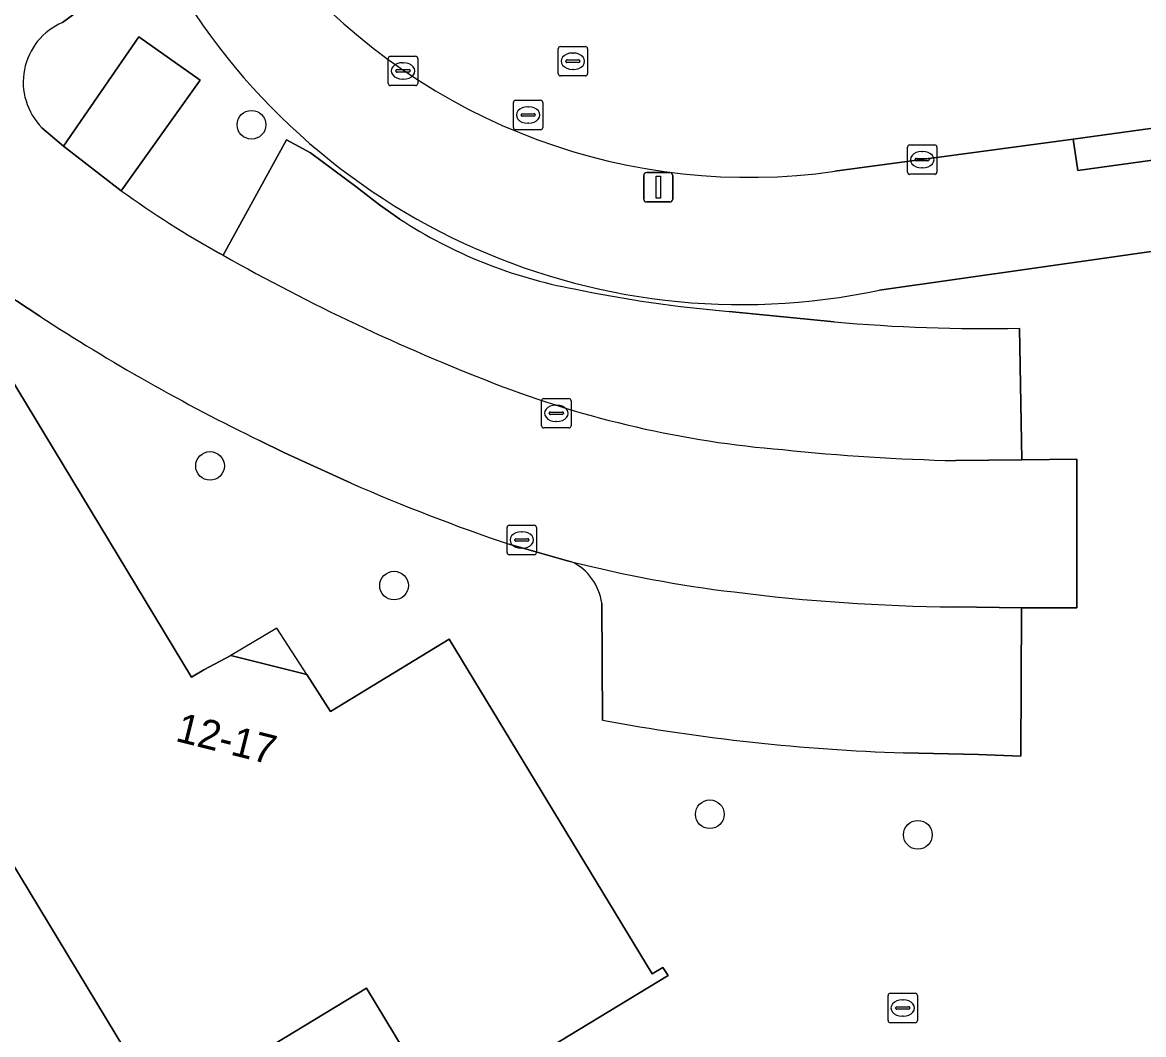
# Model space of a CAD drawing. Extents: x 158455 to 159797, y 387218 to 388672.
# Drawn here: x 158871.25 to 158909.44, y 387418.37 to 387452.85 of the extents above; entities that cross this region are included whole.
import ezdxf

# ---------------------------------------------------------------- set-up
doc = ezdxf.new("R2010")
doc.units = 0
for name, color, linetype in [('IMGEO_Boom', 7, 'Continuous'), ('IMGEO_Erf', 7, 'Continuous'), ('IMGEO_Groenvoorziening', 7, 'Continuous'), ('IMGEO_Kolk', 7, 'Continuous'), ('IMGEO_Lichtmast', 7, 'Continuous'), ('IMGEO_Pand', 7, 'Continuous'), ('IMGEO_Pand_nummerreeks', 7, 'Continuous'), ('IMGEO_Pand_overbouw', 7, 'Continuous'), ('IMGEO_Parkeervlak_open', 7, 'Continuous'), ('IMGEO_Rijbaan_lokaal_gesloten', 7, 'Continuous'), ('IMGEO_Rijbaan_lokaal_open', 7, 'Continuous'), ('IMGEO_Rioolput', 7, 'Continuous'), ('IMGEO_Voetpad_open', 7, 'Continuous')]:
    doc.layers.add(name, color=color, linetype=linetype)

msp = doc.modelspace()

# ---------------------------------------------------------------- linework, layer by layer
at = {"layer": 'IMGEO_Boom'}
for centre in [(158879.053, 387449.361), (158877.643, 387437.739), (158883.91, 387433.662), (158894.666, 387425.871), (158901.753, 387425.172)]:
    msp.add_circle(centre, 0.489, dxfattribs=at)
at = {"layer": 'IMGEO_Erf'}
for points in [[(159004.113, 387458.902), (158999.01, 387458.217), (158989.379, 387456.925), (158973.012, 387454.73), (158964.768, 387453.624), (158962.694, 387453.346), (158918.158, 387447.372), (158913.387, 387446.696), (158913.533, 387445.59), (158900.447, 387443.729)], [(158875.925, 387455.143), (158875.861, 387455.245), (158872.617, 387452.848)], [(158871.917, 387449.258), (158872.651, 387448.631), (158875.213, 387452.359), (158877.303, 387450.882), (158874.613, 387447.115)], [(158877.975, 387444.977), (158878.087, 387444.914), (158880.247, 387448.844), (158881.066, 387448.407), (158882.606, 387447.258), (158883.419, 387446.633), (158884.105, 387446.148)], [(158871.848, 387442.837), (158871.448, 387443.1), (158871.049, 387443.366)], [(158895.32, 387443.002), (158898.898, 387442.649)], [(158905.213, 387442.429), (158905.298, 387437.945), (158907.163, 387437.965), (158907.173, 387432.899), (158905.283, 387432.906), (158905.262, 387427.848), (158903.819, 387427.906), (158901.265, 387427.965)], [(158870.128, 387441.906), (158877.011, 387430.547), (158877.433, 387430.797), (158878.349, 387431.277), (158880.936, 387430.633), (158881.749, 387429.377), (158885.792, 387431.831), (158892.702, 387420.438), (158893.07, 387420.653), (158893.246, 387420.373), (158885.536, 387415.704)], [(158882.452, 387437.149), (158880.157, 387438.198), (158879.331, 387438.601)], [(158889.956, 387434.475), (158889.769, 387434.522), (158887.835, 387435.068)], [(158891.013, 387429.079), (158890.986, 387433.06)]]:
    msp.add_lwpolyline(points, dxfattribs=at)
for centre, radius, start, end in [((158895.756, 387465.7), 22.466, 208.0279, 282.052), ((158873.495, 387450.814), 2.216, 113.3331, 224.6), ((158895.375, 387476.052), 35.615, 234.3399, 240.753), ((158893.085, 387459.953), 16.469, 236.9555, 259.3652), ((158899.016, 387487.043), 44.195, 258.2902, 265.2033), ((158909.388, 387500.426), 68.744, 236.9008, 244.07226), ((158904.027, 387499.132), 56.715, 264.8113, 271.1982), ((158909.446, 387498.973), 67.46, 246.41253, 251.31572), ((158889.163, 387432.815), 1.839, 7.6405, 64.4623), ((158903.488, 387496.149), 68.221, 259.46387, 268.13308)]:
    msp.add_arc(centre, radius, start, end, dxfattribs=at)
at = {"layer": 'IMGEO_Groenvoorziening'}
msp.add_lwpolyline([(158878.756, 387417.394), (158881.325, 387413.154), (158885.536, 387415.704), (158882.967, 387419.945)], close=True, dxfattribs=at)
at = {"layer": 'IMGEO_Kolk'}
for p, q in [((158883.715, 387450.77), (158883.715, 387451.622)), ((158883.79, 387451.696), (158884.642, 387451.696)), ((158884.716, 387451.622), (158884.716, 387450.77)), ((158884.017, 387451.239), (158884.415, 387451.239)), ((158884.203, 387451.476), (158884.228, 387451.476)), ((158883.974, 387451.19), (158883.974, 387451.202)), ((158884.412, 387451.153), (158884.014, 387451.153)), ((158884.226, 387450.916), (158884.201, 387450.916)), ((158884.458, 387451.202), (158884.458, 387451.19)), ((158884.642, 387450.696), (158883.79, 387450.696)), ((158901.401, 387447.747), (158901.401, 387448.599)), ((158901.476, 387448.673), (158902.328, 387448.673)), ((158902.402, 387448.599), (158902.402, 387447.747)), ((158901.66, 387448.167), (158901.66, 387448.179)), ((158901.703, 387448.216), (158902.101, 387448.216)), ((158901.889, 387448.453), (158901.914, 387448.453)), ((158902.144, 387448.179), (158902.144, 387448.167)), ((158902.098, 387448.13), (158901.7, 387448.13)), ((158901.912, 387447.893), (158901.887, 387447.893)), ((158902.328, 387447.673), (158901.476, 387447.673)), ((158888.938, 387439.106), (158888.938, 387439.958)), ((158889.013, 387440.032), (158889.865, 387440.032)), ((158889.426, 387439.812), (158889.451, 387439.812)), ((158889.939, 387439.958), (158889.939, 387439.106)), ((158889.197, 387439.526), (158889.197, 387439.538)), ((158889.635, 387439.489), (158889.237, 387439.489)), ((158889.24, 387439.575), (158889.638, 387439.575)), ((158889.681, 387439.538), (158889.681, 387439.526)), ((158889.865, 387439.032), (158889.013, 387439.032)), ((158889.449, 387439.252), (158889.424, 387439.252)), ((158887.76, 387434.789), (158887.76, 387435.641)), ((158887.835, 387435.715), (158888.687, 387435.715)), ((158888.761, 387435.641), (158888.761, 387434.789)), ((158888.019, 387435.209), (158888.019, 387435.221)), ((158888.062, 387435.258), (158888.46, 387435.258)), ((158888.248, 387435.495), (158888.273, 387435.495)), ((158888.503, 387435.221), (158888.503, 387435.209)), ((158888.457, 387435.172), (158888.059, 387435.172)), ((158888.271, 387434.935), (158888.246, 387434.935)), ((158888.687, 387434.715), (158887.835, 387434.715)), ((158900.737, 387418.845), (158900.737, 387419.697)), ((158900.812, 387419.771), (158901.664, 387419.771)), ((158901.225, 387419.551), (158901.25, 387419.551)), ((158901.738, 387419.697), (158901.738, 387418.845)), ((158900.996, 387419.265), (158900.996, 387419.277)), ((158901.434, 387419.228), (158901.036, 387419.228)), ((158901.039, 387419.314), (158901.437, 387419.314)), ((158901.48, 387419.277), (158901.48, 387419.265)), ((158901.664, 387418.771), (158900.812, 387418.771)), ((158901.248, 387418.991), (158901.223, 387418.991))]:
    msp.add_line(p, q, dxfattribs=at)
for points in [[(158883.715, 387450.77), (158883.715, 387451.622)], [(158883.79, 387451.696), (158884.642, 387451.696)], [(158884.716, 387451.622), (158884.716, 387450.77)], [(158884.642, 387450.696), (158883.79, 387450.696)], [(158901.401, 387447.747), (158901.401, 387448.599)], [(158901.476, 387448.673), (158902.328, 387448.673)], [(158902.402, 387448.599), (158902.402, 387447.747)], [(158902.328, 387447.673), (158901.476, 387447.673)], [(158888.938, 387439.106), (158888.938, 387439.958)], [(158889.013, 387440.032), (158889.865, 387440.032)], [(158889.939, 387439.958), (158889.939, 387439.106)], [(158889.865, 387439.032), (158889.013, 387439.032)], [(158887.76, 387434.789), (158887.76, 387435.641)], [(158887.835, 387435.715), (158888.687, 387435.715)], [(158888.761, 387435.641), (158888.761, 387434.789)], [(158888.687, 387434.715), (158887.835, 387434.715)], [(158900.737, 387418.845), (158900.737, 387419.697)], [(158900.812, 387419.771), (158901.664, 387419.771)], [(158901.738, 387419.697), (158901.738, 387418.845)], [(158901.664, 387418.771), (158900.812, 387418.771)]]:
    msp.add_lwpolyline(points, dxfattribs=at)
for centre, radius, start, end in [((158883.792, 387451.62), 0.0765, 91.552, 178.448), ((158883.792, 387451.62), 0.0765, 91.552, 178.448), ((158884.64, 387451.62), 0.0765, 1.552, 88.448), ((158884.64, 387451.62), 0.0765, 1.552, 88.448), ((158884.014, 387451.199), 0.0403, 85.8775, 175.7526), ((158884.419, 387451.201), 0.0386, 1.7309, 96.639), ((158884.011, 387451.189), 0.0366, 178.938, 274.7102), ((158884.415, 387451.196), 0.043, 264.8664, 352.4533), ((158883.792, 387450.772), 0.0765, 181.552, 268.448), ((158883.792, 387450.772), 0.0765, 181.552, 268.448), ((158884.64, 387450.772), 0.0765, 271.552, 358.448), ((158884.64, 387450.772), 0.0765, 271.552, 358.448), ((158901.478, 387448.597), 0.0765, 91.552, 178.448), ((158901.478, 387448.597), 0.0765, 91.552, 178.448), ((158902.326, 387448.597), 0.0765, 1.552, 88.448), ((158902.326, 387448.597), 0.0765, 1.552, 88.448), ((158901.7, 387448.176), 0.0403, 85.8775, 175.7526), ((158902.105, 387448.178), 0.0386, 1.7309, 96.639), ((158901.697, 387448.166), 0.0366, 178.938, 274.7102), ((158902.101, 387448.173), 0.043, 264.8664, 352.4533), ((158901.478, 387447.749), 0.0765, 181.552, 268.448), ((158901.478, 387447.749), 0.0765, 181.552, 268.448), ((158902.326, 387447.749), 0.0765, 271.552, 358.448), ((158902.326, 387447.749), 0.0765, 271.552, 358.448), ((158889.015, 387439.956), 0.0765, 91.552, 178.448), ((158889.015, 387439.956), 0.0765, 91.552, 178.448), ((158889.863, 387439.956), 0.0765, 1.552, 88.448), ((158889.863, 387439.956), 0.0765, 1.552, 88.448), ((158889.237, 387439.535), 0.0403, 85.8775, 175.7526), ((158889.234, 387439.525), 0.0366, 178.938, 274.7102), ((158889.638, 387439.532), 0.043, 264.8664, 352.4533), ((158889.642, 387439.537), 0.0386, 1.7309, 96.639), ((158889.015, 387439.108), 0.0765, 181.552, 268.448), ((158889.015, 387439.108), 0.0765, 181.552, 268.448), ((158889.863, 387439.108), 0.0765, 271.552, 358.448), ((158889.863, 387439.108), 0.0765, 271.552, 358.448), ((158887.837, 387435.639), 0.0765, 91.552, 178.448), ((158887.837, 387435.639), 0.0765, 91.552, 178.448), ((158888.685, 387435.639), 0.0765, 1.552, 88.448), ((158888.685, 387435.639), 0.0765, 1.552, 88.448), ((158888.059, 387435.218), 0.0403, 85.8775, 175.7526), ((158888.056, 387435.208), 0.0366, 178.938, 274.7102), ((158888.46, 387435.215), 0.043, 264.8664, 352.4533), ((158888.464, 387435.22), 0.0386, 1.7309, 96.639), ((158887.837, 387434.791), 0.0765, 181.552, 268.448), ((158887.837, 387434.791), 0.0765, 181.552, 268.448), ((158888.685, 387434.791), 0.0765, 271.552, 358.448), ((158888.685, 387434.791), 0.0765, 271.552, 358.448), ((158900.814, 387419.695), 0.0765, 91.552, 178.448), ((158900.814, 387419.695), 0.0765, 91.552, 178.448), ((158901.662, 387419.695), 0.0765, 1.552, 88.448), ((158901.662, 387419.695), 0.0765, 1.552, 88.448), ((158901.036, 387419.274), 0.0403, 85.8775, 175.7526), ((158901.033, 387419.264), 0.0366, 178.938, 274.7102), ((158901.437, 387419.271), 0.043, 264.8664, 352.4533), ((158901.441, 387419.276), 0.0386, 1.7309, 96.639), ((158900.814, 387418.847), 0.0765, 181.552, 268.448), ((158900.814, 387418.847), 0.0765, 181.552, 268.448), ((158901.662, 387418.847), 0.0765, 271.552, 358.448), ((158901.662, 387418.847), 0.0765, 271.552, 358.448)]:
    msp.add_arc(centre, radius, start, end, dxfattribs=at)
for centre, major_axis, ratio, start_param, end_param in [((158884.202, 387451.196), (-0.387, 0.002), 0.722429, 4.712389, 7.853982), ((158884.227, 387451.196), (-0.39, 0.002), 0.717154, 1.570796, 4.712389), ((158901.888, 387448.173), (-0.387, 0.002), 0.722429, 4.712389, 7.853982), ((158901.913, 387448.173), (-0.39, 0.002), 0.717154, 1.570796, 4.712389), ((158889.425, 387439.532), (-0.387, 0.002), 0.722429, 4.712389, 7.853982), ((158889.45, 387439.532), (-0.39, 0.002), 0.717154, 1.570796, 4.712389), ((158888.247, 387435.215), (-0.387, 0.002), 0.722429, 4.712389, 7.853982), ((158888.272, 387435.215), (-0.39, 0.002), 0.717154, 1.570796, 4.712389), ((158901.224, 387419.271), (-0.387, 0.002), 0.722429, 4.712389, 7.853982), ((158901.249, 387419.271), (-0.39, 0.002), 0.717154, 1.570796, 4.712389)]:
    msp.add_ellipse(centre, major_axis=major_axis, ratio=ratio, start_param=start_param, end_param=end_param, dxfattribs=at)
at = {"layer": 'IMGEO_Lichtmast'}
for p, q in [((158892.416, 387446.832), (158892.416, 387447.632)), ((158892.416, 387447.632), (158892.416, 387446.832)), ((158892.516, 387447.732), (158893.306, 387447.732)), ((158893.306, 387447.732), (158892.516, 387447.732)), ((158893.406, 387447.632), (158893.406, 387446.832)), ((158893.406, 387446.832), (158893.406, 387447.632)), ((158893.306, 387446.732), (158892.516, 387446.732)), ((158892.516, 387446.732), (158893.306, 387446.732))]:
    msp.add_line(p, q, dxfattribs=at)
msp.add_lwpolyline([(158892.836, 387447.607), (158892.986, 387447.607), (158892.986, 387446.857), (158892.836, 387446.857), (158892.836, 387447.607)], dxfattribs=at)
for centre, start, end in [((158892.516, 387447.632), 90, 180), ((158892.516, 387447.632), 90, 180), ((158893.306, 387447.632), 0, 90), ((158893.306, 387447.632), 360, 90), ((158892.516, 387446.832), 180, 270), ((158892.516, 387446.832), 180, 270), ((158893.306, 387446.832), 270, 0), ((158893.306, 387446.832), 270, 0)]:
    msp.add_arc(centre, 0.1, start, end, dxfattribs=at)
at = {"layer": 'IMGEO_Pand'}
for points in [[(158876.19, 387415.839), (158878.756, 387417.394), (158882.967, 387419.945), (158885.536, 387415.704), (158893.246, 387420.373), (158893.07, 387420.653), (158892.702, 387420.438), (158885.792, 387431.831), (158881.749, 387429.377), (158880.936, 387430.633), (158878.349, 387431.277), (158877.433, 387430.797), (158877.011, 387430.547), (158870.128, 387441.906), (158863.221, 387437.75), (158862.731, 387437.455), (158865.617, 387432.671), (158867.166, 387430.102), (158867.288, 387430.172), (158876.018, 387415.735)], [(158876.19, 387415.839), (158876.018, 387415.735), (158867.288, 387430.172), (158867.166, 387430.102), (158862.332, 387427.187), (158861.702, 387428.232), (158861.172, 387427.912), (158860.62, 387428.828), (158861.15, 387429.148), (158860.783, 387429.756), (158858.526, 387433.498), (158851.265, 387429.143), (158855.262, 387422.534), (158856.931, 387423.54), (158869.412, 387402.893), (158880.123, 387409.348), (158879.537, 387410.315)]]:
    msp.add_lwpolyline(points, close=True, dxfattribs=at)
at = {"layer": 'IMGEO_Pand_overbouw'}
msp.add_lwpolyline([(158879.918, 387432.206), (158878.349, 387431.277), (158880.936, 387430.633)], close=True, dxfattribs=at)
at = {"layer": 'IMGEO_Parkeervlak_open'}
msp.add_lwpolyline([(158877.303, 387450.882), (158875.213, 387452.359), (158872.651, 387448.631), (158874.613, 387447.115)], close=True, dxfattribs=at)
for points in [[(158884.105, 387446.148), (158883.419, 387446.633), (158882.606, 387447.258), (158881.066, 387448.407), (158880.247, 387448.844), (158878.087, 387444.914)], [(158898.898, 387442.649), (158895.32, 387443.002)], [(158903.048, 387437.92), (158905.298, 387437.945), (158905.213, 387442.429)], [(158890.986, 387433.06), (158891.013, 387429.079)], [(158901.265, 387427.965), (158903.819, 387427.906), (158905.262, 387427.848), (158905.283, 387432.906), (158902.988, 387432.936)]]:
    msp.add_lwpolyline(points, dxfattribs=at)
for centre, radius, start, end in [((158893.085, 387459.953), 16.469, 236.9555, 259.3652), ((158912.992, 387506.857), 71.101, 240.59836, 248.83577), ((158899.016, 387487.043), 44.195, 258.2902, 265.2033), ((158904.027, 387499.132), 56.715, 264.8113, 271.1982), ((158899.982, 387473.124), 34.946, 248.7602, 265.3553), ((158904.496, 387507.598), 69.693, 263.95092, 268.80929), ((158900.785, 387477.245), 44.12, 255.7914, 263.1093), ((158889.163, 387432.815), 1.839, 7.6405, 64.4623), ((158903.686, 387498.789), 65.857, 262.85301, 269.39304), ((158903.488, 387496.149), 68.221, 259.46387, 268.13308)]:
    msp.add_arc(centre, radius, start, end, dxfattribs=at)
at = {"layer": 'IMGEO_Rijbaan_lokaal_gesloten'}
msp.add_lwpolyline([(158898.93, 387447.778), (158907.04, 387448.873), (158912.798, 387449.665), (158912.567, 387451.122), (158994.092, 387462.187)], dxfattribs=at)
msp.add_arc((158895.992, 387468.359), 20.79, 221.2558, 278.1232, dxfattribs=at)
at = {"layer": 'IMGEO_Rijbaan_lokaal_open'}
for points in [[(158872.617, 387452.848), (158875.861, 387455.245), (158872.628, 387460.413), (158853.054, 387445.81), (158834.448, 387431.91), (158827.832, 387426.967), (158817.674, 387419.378)], [(158874.613, 387447.115), (158872.651, 387448.631), (158871.917, 387449.258)], [(158841.258, 387429.496), (158843.407, 387431.102), (158865.405, 387447.54), (158865.534, 387447.366), (158868.364, 387443.543), (158869.559, 387444.453), (158871.049, 387443.366), (158871.448, 387443.1), (158871.848, 387442.837)], [(158878.087, 387444.914), (158877.975, 387444.977)], [(158879.331, 387438.601), (158880.157, 387438.198), (158882.452, 387437.149)], [(158902.988, 387432.936), (158905.283, 387432.906), (158907.173, 387432.899), (158907.163, 387437.965), (158905.298, 387437.945), (158903.048, 387437.92)], [(158887.835, 387435.068), (158889.769, 387434.522), (158889.956, 387434.475)]]:
    msp.add_lwpolyline(points, dxfattribs=at)
for centre, radius, start, end in [((158873.495, 387450.814), 2.216, 113.3331, 224.6), ((158895.375, 387476.052), 35.615, 234.3399, 240.753), ((158912.992, 387506.857), 71.101, 240.59836, 248.83577), ((158909.388, 387500.426), 68.744, 236.9008, 244.07226), ((158899.982, 387473.124), 34.946, 248.7602, 265.3553), ((158904.496, 387507.598), 69.693, 263.95092, 268.80929), ((158909.446, 387498.973), 67.46, 246.41253, 251.31572), ((158900.785, 387477.245), 44.12, 255.7914, 263.1093), ((158903.686, 387498.789), 65.857, 262.85301, 269.39304)]:
    msp.add_arc(centre, radius, start, end, dxfattribs=at)
at = {"layer": 'IMGEO_Rioolput'}
for p, q in [((158889.575, 387452.026), (158890.427, 387452.026)), ((158889.5, 387451.1), (158889.5, 387451.952)), ((158889.988, 387451.806), (158890.013, 387451.806)), ((158890.501, 387451.952), (158890.501, 387451.1)), ((158889.759, 387451.52), (158889.759, 387451.532)), ((158890.197, 387451.483), (158889.799, 387451.483)), ((158889.802, 387451.569), (158890.2, 387451.569)), ((158890.011, 387451.246), (158889.986, 387451.246)), ((158890.243, 387451.532), (158890.243, 387451.52)), ((158890.427, 387451.026), (158889.575, 387451.026)), ((158887.976, 387449.268), (158887.976, 387450.12)), ((158888.051, 387450.194), (158888.903, 387450.194)), ((158888.977, 387450.12), (158888.977, 387449.268)), ((158888.278, 387449.737), (158888.676, 387449.737)), ((158888.464, 387449.974), (158888.489, 387449.974)), ((158888.235, 387449.688), (158888.235, 387449.7)), ((158888.673, 387449.651), (158888.275, 387449.651)), ((158888.487, 387449.414), (158888.462, 387449.414)), ((158888.719, 387449.7), (158888.719, 387449.688)), ((158888.903, 387449.194), (158888.051, 387449.194))]:
    msp.add_line(p, q, dxfattribs=at)
for points in [[(158889.575, 387452.026), (158890.427, 387452.026)], [(158889.5, 387451.1), (158889.5, 387451.952)], [(158890.501, 387451.952), (158890.501, 387451.1)], [(158890.427, 387451.026), (158889.575, 387451.026)], [(158887.976, 387449.268), (158887.976, 387450.12)], [(158888.051, 387450.194), (158888.903, 387450.194)], [(158888.977, 387450.12), (158888.977, 387449.268)], [(158888.903, 387449.194), (158888.051, 387449.194)]]:
    msp.add_lwpolyline(points, dxfattribs=at)
for centre, radius, start, end in [((158889.577, 387451.95), 0.0765, 91.552, 178.448), ((158889.577, 387451.95), 0.0765, 91.552, 178.448), ((158890.425, 387451.95), 0.0765, 1.552, 88.448), ((158890.425, 387451.95), 0.0765, 1.552, 88.448), ((158889.799, 387451.529), 0.0403, 85.8775, 175.7526), ((158889.796, 387451.519), 0.0366, 178.938, 274.7102), ((158890.2, 387451.526), 0.043, 264.8664, 352.4533), ((158890.204, 387451.531), 0.0386, 1.7309, 96.639), ((158889.577, 387451.102), 0.0765, 181.552, 268.448), ((158889.577, 387451.102), 0.0765, 181.552, 268.448), ((158890.425, 387451.102), 0.0765, 271.552, 358.448), ((158890.425, 387451.102), 0.0765, 271.552, 358.448), ((158888.053, 387450.118), 0.0765, 91.552, 178.448), ((158888.053, 387450.118), 0.0765, 91.552, 178.448), ((158888.901, 387450.118), 0.0765, 1.552, 88.448), ((158888.901, 387450.118), 0.0765, 1.552, 88.448), ((158888.275, 387449.697), 0.0403, 85.8775, 175.7526), ((158888.68, 387449.699), 0.0386, 1.7309, 96.639), ((158888.272, 387449.687), 0.0366, 178.938, 274.7102), ((158888.676, 387449.694), 0.043, 264.8664, 352.4533), ((158888.053, 387449.27), 0.0765, 181.552, 268.448), ((158888.053, 387449.27), 0.0765, 181.552, 268.448), ((158888.901, 387449.27), 0.0765, 271.552, 358.448), ((158888.901, 387449.27), 0.0765, 271.552, 358.448)]:
    msp.add_arc(centre, radius, start, end, dxfattribs=at)
for centre, major_axis, ratio, start_param, end_param in [((158889.987, 387451.526), (-0.387, 0.002), 0.722429, 4.712389, 7.853982), ((158890.012, 387451.526), (-0.39, 0.002), 0.717154, 1.570796, 4.712389), ((158888.463, 387449.694), (-0.387, 0.002), 0.722429, 4.712389, 7.853982), ((158888.488, 387449.694), (-0.39, 0.002), 0.717154, 1.570796, 4.712389)]:
    msp.add_ellipse(centre, major_axis=major_axis, ratio=ratio, start_param=start_param, end_param=end_param, dxfattribs=at)
at = {"layer": 'IMGEO_Voetpad_open'}
for points in [[(158900.447, 387443.729), (158913.533, 387445.59), (158913.387, 387446.696), (158918.158, 387447.372), (158962.694, 387453.346), (158964.768, 387453.624), (158973.012, 387454.73), (158989.379, 387456.925)], [(158915, 387449.968), (158912.798, 387449.665), (158907.04, 387448.873), (158907.199, 387447.804), (158915.161, 387448.908), (158915.099, 387449.428), (158915.448, 387449.312), (158917.307, 387447.986)], [(158917.307, 387447.986), (158915.448, 387449.312), (158915.099, 387449.428), (158915.161, 387448.908), (158907.199, 387447.804), (158907.04, 387448.873), (158898.93, 387447.778)]]:
    msp.add_lwpolyline(points, dxfattribs=at)
for centre, radius, start, end in [((158895.756, 387465.7), 22.466, 208.0279, 282.052), ((158895.992, 387468.359), 20.79, 221.2558, 278.1232)]:
    msp.add_arc(centre, radius, start, end, dxfattribs=at)

# ---------------------------------------------------------------- texts
at = {"layer": 'IMGEO_Pand_nummerreeks'}
msp.add_text('12-17', height=1, rotation=346.028, dxfattribs=at).set_placement((158876.429, 387428.374))

doc.saveas('drawing.dxf')
